(* Logix 5000 project; controller ICX35_AOI_1_8 1756-L63 rev 16.23; software revision 16.04 *)

TASK MainTask (continuous, watchdog 500 ms) : MainProgram

MODULES
   Local : 1756-L63 (ICP 0, rev 16.23)
      for_local_ICX35 : 1756-EN2T (ICP 1, Ethernet 192.160.0.246, rev 2.1)
         ICX35 : vendor 1 type 0 code 23 (Ethernet 192.168.0.250, rev 1.1)
END_MODULES

TYPE ICX35_CONTROL :   // Contains trigger bits for the functions supported by the ICX35. Bit should be set as 1 to trigger request and AOI will automa
STRUCT
   Get_Status : BOOL;   // Reads status data from ICX35
   Reset_Status : BOOL;   // Resets status counters from ICX35
   Write_SMS : BOOL;   // Sends SMS message to ICX35
   Read_SMS : BOOL;   // Reads SMS message from ICX35
   Clear_SMS : BOOL;   // Clears all SMS from ICX35
   Reboot : BOOL;   // Reboot ICX35
END_STRUCT
END_TYPE

TYPE ICX35_ModuleDef :   // Main ICX35 definition
STRUCT
   CONTROL : ICX35_CONTROL;   // Trigger bits used to request functions from ICX35
   STATUS : ICX35_STATUS;   // ICX35 status
   SMS : ICX35_SMS;   // SMS send and receive functions
   UTIL : ICX35_UTIL;   // Tags used for internal processing - do not update the values
END_STRUCT
END_TYPE

TYPE ICX35_SMS :   // Stores main SMS functions
STRUCT
   READ : ICX35_SMS_Read;   // Reads SMS data from ICX35
   WRITE : ICX35_SMS_Write;   // Writes SMS message to ICX35
END_STRUCT
END_TYPE

TYPE ICX35_SMS_Read :   // SMS data read from ICX35
STRUCT
   Date_Time : SINT[18];   // DateTime Stamp for received SMS text. MM/DD/YY HH:MM:SS
   Time_Zone : SINT[6];   // UTC =/- TZ
   Phone_Number : SINT[24];   // full number including prefixes country code etc..
   Message : SINT[160];   // Received the message text
END_STRUCT
END_TYPE

TYPE ICX35_SMS_Write :   // SMS data written to ICX35
STRUCT
   Message : LSTRING;
   Phone_Count : INT;   // Quantity of phone numbers that the SMS will be sent to. 5 is the limit.
   Phone_Number_1 : SINT[24];   // full number including prefixes country code (example +16613334455)
   Phone_Number_2 : SINT[24];   // full number including prefixes country code
   Phone_Number_3 : SINT[24];   // full number including prefixes country code
   Phone_Number_4 : SINT[24];   // full number including prefixes country code
   Phone_Number_5 : SINT[24];   // full number including prefixes country code
END_STRUCT
END_TYPE

TYPE ICX35_STATUS :   // ICX35 Status
STRUCT
   RSSI : SINT;   // Current Signal Strength dBm. Range -50 to -125
   Min_RSSI : SINT;   // Signal Strength Minimum(since power on). Range -50 to -125
   Max_RSSI : SINT;   // Signal Strength Maximum(since power on). Range -50 to -125
   Cell_Net_State : SINT;   // Status of the connection to the Cellular Network. 0: Disconnect, 1: Connecting, 2: Connected
   MAC_Address : SINT[6];   // MAC ID of ICX35
   WAN_IP : INT[4];   // Cellular network IP
   Cell_Net_Disconnects : DINT;   // Number of times Modem is disconnected from the cellular network since power on
   LAN_KBytes_Sent : DINT;   // Number Kbytes sent on LAN since power on
   LAN_KBytes_Received : DINT;   // Number of Kbytes received LAN since power on
   WAN_KBytes_Sent : DINT;   // Number of Bytes Sent WAN since power on
   WAN_KBytes_Received : DINT;   // Number of bytes received WAN since power on
   SMS_MSGs_Sent : DINT;   // Number of SMS Messages Sent since power on
   SMS_MSGs_Received : DINT;   // Number of SMS Messages Sent since power on
   SMS_MSGs_Rx_Free_Buffer_Counter : DINT;   // Number of free slots in the Rx SMS buffer out of 255 Message slots.
   PowerOnTime_Year : INT;   // Power on time year
   PowerOnTime_Month : INT;   // Power on time month
   PowerOnTime_Day : INT;   // Power on time day
   PowerOnTime_Hour : INT;   // Power on time hour
   PowerOnTime_Minute : INT;   // Power on time minute
   PowerOnTime_Second : INT;   // Power on time second
   Link_Time_Days : DINT;   // Link Time: Days of Cellular Connection.
   Link_Time_Hours : DINT;   // Link Time: Hours of Cellular Connection.
   Link_Time_Minutes : INT;   // Link Time: Minutes of Cellular Connection.
   Link_Time_Seconds : INT;   // Link Time: Seconds of Cellular Connection.
   Data_Usage_Current_Month : DINT;   // Data usage of current month in KB.
   Data_Usage_Previous_Month : DINT;   // Data usage of last month in KB.
   Data_Usage_Current_Day : DINT;   // Data usage for today in KB.
   Data_Usage_Previous_Day : DINT;   // Data usage of yesterday in KB.
   FW_Version : SINT[24];   // Firmware Version for the Gateway
   Phone_Number : SINT[18];   // Cellular phone number
   IMEI : SINT[20];   // IMEI number
END_STRUCT
END_TYPE

TYPE ICX35_UTIL :   // Internal tag used for internal ladder processing. Not to be updated by user application
STRUCT
   Status : SINT[149];   // Receives Raw Status Data from the Gateway
   SMSwrite : SINT[284];   // Text Messages (SMS) to be sent.
   SMSread : SINT[216];   // Text Messages that are read.
   SMSwritemsgstat : BOOL;   // SMS Write MSG instruction status.
   SMSreadmsgstat : BOOL;   // SMS Read MSG instruction status.
   ResetStatus : SINT;   // Reset speceific Status counters.
   Clear_SMS : SINT;   // Clear SMS Messages
   Reboot : SINT;   // Reboot ICX35 Gateway
END_STRUCT
END_TYPE

TYPE LSTRING :   // string type
STRUCT
   LEN : DINT;
   DATA : SINT[160];
END_STRUCT
END_TYPE

ADD_ON_INSTRUCTION AOI_ICX35   (* revision 1.8 *)
// Add-On Instruction for ICX35 Industrial Cellular Gateway
// Revision note:
// 1.8    2018/06/14.
// This Revision is compatible with ICX35 firmware version 1.4 and later.
VAR_IN_OUT
   ICX35 : ICX35_ModuleDef; {required}
   ICX35_MSG_GET_STATUS : MESSAGE; {required}
   ICX35_MSG_READ_SMS : MESSAGE; {required}
   ICX35_MSG_RESET_STATUS : MESSAGE; {required}
   ICX35_MSG_WRITE_SMS : MESSAGE; {required}
   ICX35_MSG_CLEAR_SMS : MESSAGE; {required}
   ICX35_MSG_REBOOT : MESSAGE; {required}
END_VAR

ROUTINE Logic   (* ladder *)
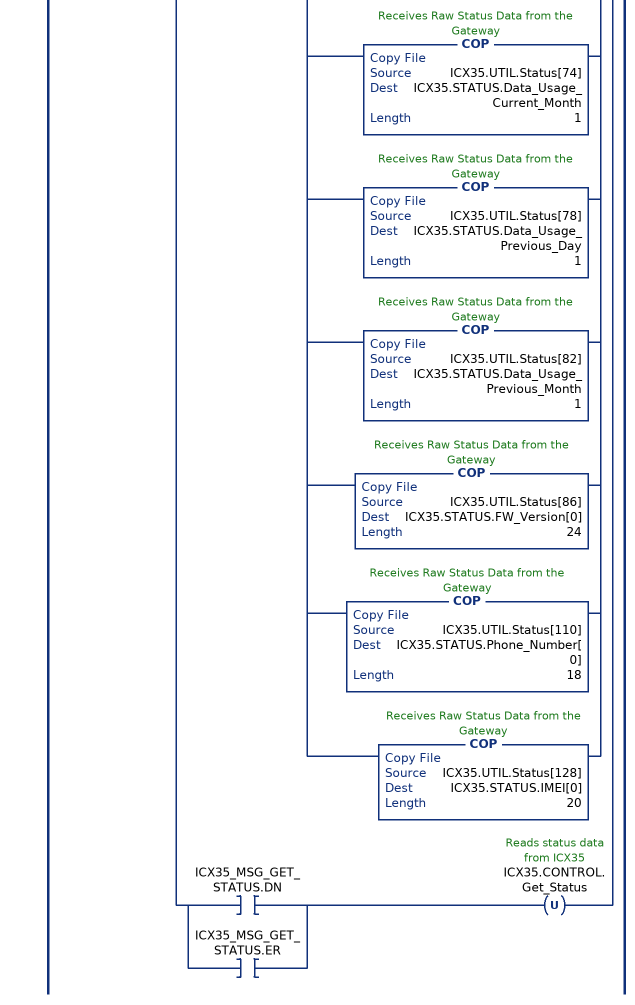
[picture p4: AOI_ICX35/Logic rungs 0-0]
   0: XIC(ICX35.CONTROL.Get_Status)[MSG(ICX35_MSG_GET_STATUS) ,XIC(ICX35_MSG_GET_STATUS.DN) [COP(ICX35.UTIL.Status[0],ICX35.STATUS.RSSI,4) ,COP(ICX35.UTIL.Status[4],ICX35.STATUS.MAC_Address[0],6) ,MVM(0,65280,ICX35.STATUS.WAN_IP[0]) ,MVM(ICX35.UTIL.Status[10],255,ICX35.STATUS.WAN_IP[0]) ,MVM(0,65280,ICX35.STATUS.WAN_IP[1]) ,MVM(ICX35.UTIL.Status[11],255,ICX35.STATUS.WAN_IP[1]) ,MVM(0,65280,ICX35.STATUS.WAN_IP[2]) ,MVM(ICX35.UTIL.Status[12],255,ICX35.STATUS.WAN_IP[2]) ,MVM(0,65280,ICX35.STATUS.WAN_IP[3]) ,MVM(ICX35.UTIL.Status[13],255,ICX35.STATUS.WAN_IP[3]) ,COP(ICX35.UTIL.Status[14],ICX35.STATUS.Cell_Net_Disconnects,1) ,COP(ICX35.UTIL.Status[18],ICX35.STATUS.LAN_KBytes_Sent,1) ,COP(ICX35.UTIL.Status[22],ICX35.STATUS.LAN_KBytes_Received,1) ,COP(ICX35.UTIL.Status[26],ICX35.STATUS.WAN_KBytes_Sent,1) ,COP(ICX35.UTIL.Status[30],ICX35.STATUS.WAN_KBytes_Received,1) ,COP(ICX35.UTIL.Status[34],ICX35.STATUS.SMS_MSGs_Sent,1) ,COP(ICX35.UTIL.Status[38],ICX35.STATUS.SMS_MSGs_Received,1) ,COP(ICX35.UTIL.Status[42],ICX35.STATUS.SMS_MSGs_Rx_Free_Buffer_Counter,1) ,COP(ICX35.UTIL.Status[46],ICX35.STATUS.PowerOnTime_Year,1) ,COP(ICX35.UTIL.Status[48],ICX35.STATUS.PowerOnTime_Month,1) ,COP(ICX35.UTIL.Status[50],ICX35.STATUS.PowerOnTime_Day,1) ,COP(ICX35.UTIL.Status[52],ICX35.STATUS.PowerOnTime_Hour,1) ,COP(ICX35.UTIL.Status[54],ICX35.STATUS.PowerOnTime_Minute,1) ,COP(ICX35.UTIL.Status[56],ICX35.STATUS.PowerOnTime_Second,1) ,COP(ICX35.UTIL.Status[58],ICX35.STATUS.Link_Time_Days,1) ,COP(ICX35.UTIL.Status[62],ICX35.STATUS.Link_Time_Hours,1) ,COP(ICX35.UTIL.Status[66],ICX35.STATUS.Link_Time_Minutes,1) ,COP(ICX35.UTIL.Status[68],ICX35.STATUS.Link_Time_Seconds,1) ,COP(ICX35.UTIL.Status[70],ICX35.STATUS.Data_Usage_Current_Day,1) ,COP(ICX35.UTIL.Status[74],ICX35.STATUS.Data_Usage_Current_Month,1) ,COP(ICX35.UTIL.Status[78],ICX35.STATUS.Data_Usage_Previous_Day,1) ,COP(ICX35.UTIL.Status[82],ICX35.STATUS.Data_Usage_Previous_Month,1) ,COP(ICX35.UTIL.Status[86],ICX35.STATUS.FW_Version[0],24) ,COP(ICX35.UTIL.Status[110],ICX35.STATUS.Phone_Number[0],18) ,COP(ICX35.UTIL.Status[128],ICX35.STATUS.IMEI[0],20) ] ,[XIC(ICX35_MSG_GET_STATUS.DN) ,XIC(ICX35_MSG_GET_STATUS.ER) ] OTU(ICX35.CONTROL.Get_Status) ];
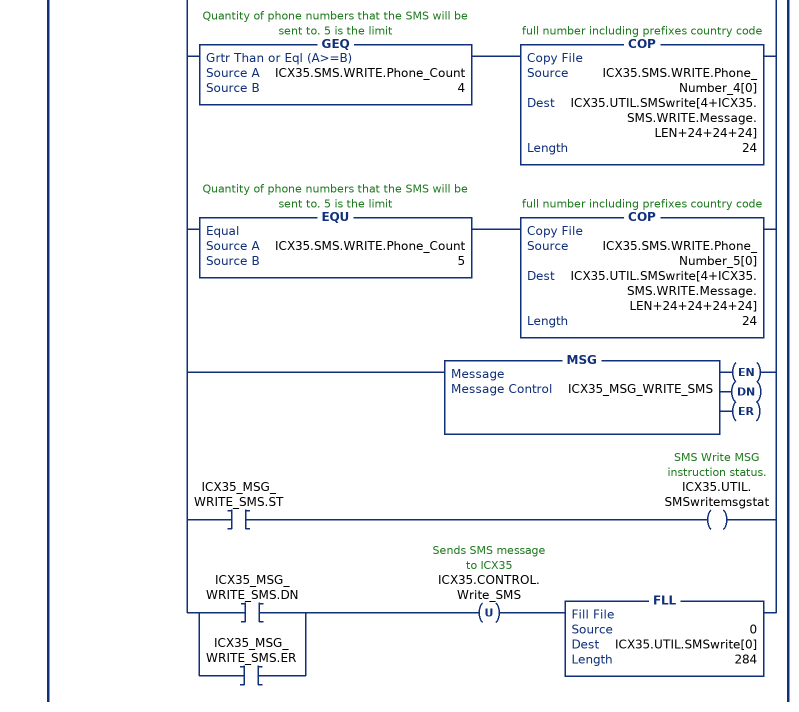
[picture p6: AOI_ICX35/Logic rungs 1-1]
   1: XIC(ICX35.CONTROL.Write_SMS)[LEQ(ICX35.SMS.WRITE.Message.LEN,160) COP(ICX35.SMS.WRITE.Message.LEN,ICX35.UTIL.SMSwrite[0],2) ,COP(ICX35.SMS.WRITE.Phone_Count,ICX35.UTIL.SMSwrite[2],2) ,COP(ICX35.SMS.WRITE.Message.DATA[0],ICX35.UTIL.SMSwrite[4],ICX35.SMS.WRITE.Message.LEN) ,COP(ICX35.SMS.WRITE.Phone_Number_1[0],ICX35.UTIL.SMSwrite[4+ICX35.SMS.WRITE.Message.LEN],24) ,GEQ(ICX35.SMS.WRITE.Phone_Count,2) COP(ICX35.SMS.WRITE.Phone_Number_2[0],ICX35.UTIL.SMSwrite[4+ICX35.SMS.WRITE.Message.LEN+24],24) ,GEQ(ICX35.SMS.WRITE.Phone_Count,3) COP(ICX35.SMS.WRITE.Phone_Number_3[0],ICX35.UTIL.SMSwrite[4+ICX35.SMS.WRITE.Message.LEN+24+24],24) ,GEQ(ICX35.SMS.WRITE.Phone_Count,4) COP(ICX35.SMS.WRITE.Phone_Number_4[0],ICX35.UTIL.SMSwrite[4+ICX35.SMS.WRITE.Message.LEN+24+24+24],24) ,EQU(ICX35.SMS.WRITE.Phone_Count,5) COP(ICX35.SMS.WRITE.Phone_Number_5[0],ICX35.UTIL.SMSwrite[4+ICX35.SMS.WRITE.Message.LEN+24+24+24+24],24) ,MSG(ICX35_MSG_WRITE_SMS) ,XIC(ICX35_MSG_WRITE_SMS.ST) OTE(ICX35.UTIL.SMSwritemsgstat) ,[XIC(ICX35_MSG_WRITE_SMS.DN) ,XIC(ICX35_MSG_WRITE_SMS.ER) ] OTU(ICX35.CONTROL.Write_SMS) FLL(0,ICX35.UTIL.SMSwrite[0],284) ];
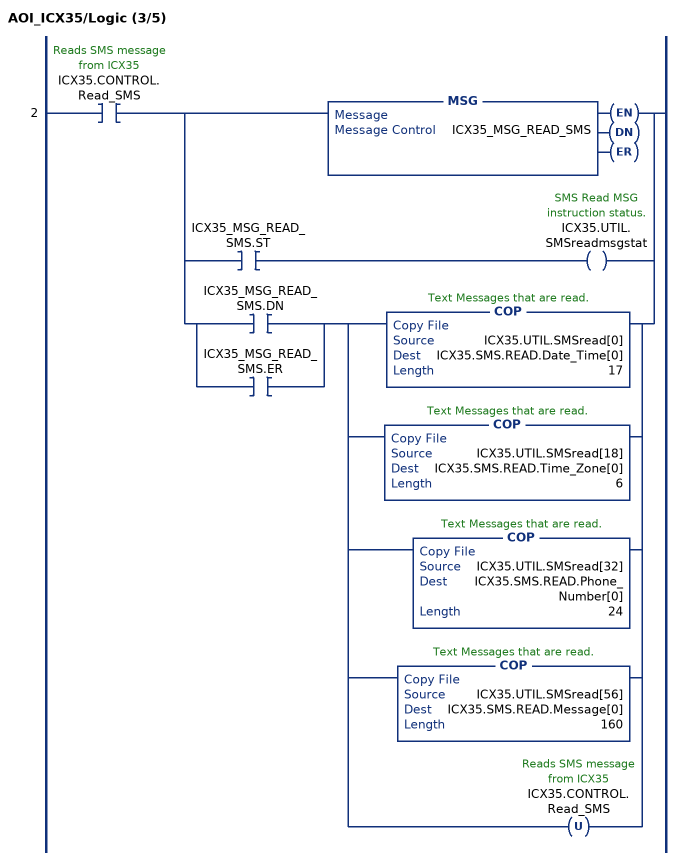
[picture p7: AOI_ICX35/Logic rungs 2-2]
   2: XIC(ICX35.CONTROL.Read_SMS)[MSG(ICX35_MSG_READ_SMS) ,XIC(ICX35_MSG_READ_SMS.ST) OTE(ICX35.UTIL.SMSreadmsgstat) ,[XIC(ICX35_MSG_READ_SMS.DN) ,XIC(ICX35_MSG_READ_SMS.ER) ] [COP(ICX35.UTIL.SMSread[0],ICX35.SMS.READ.Date_Time[0],17) ,COP(ICX35.UTIL.SMSread[18],ICX35.SMS.READ.Time_Zone[0],6) ,COP(ICX35.UTIL.SMSread[32],ICX35.SMS.READ.Phone_Number[0],24) ,COP(ICX35.UTIL.SMSread[56],ICX35.SMS.READ.Message[0],160) ,OTU(ICX35.CONTROL.Read_SMS) ] ];
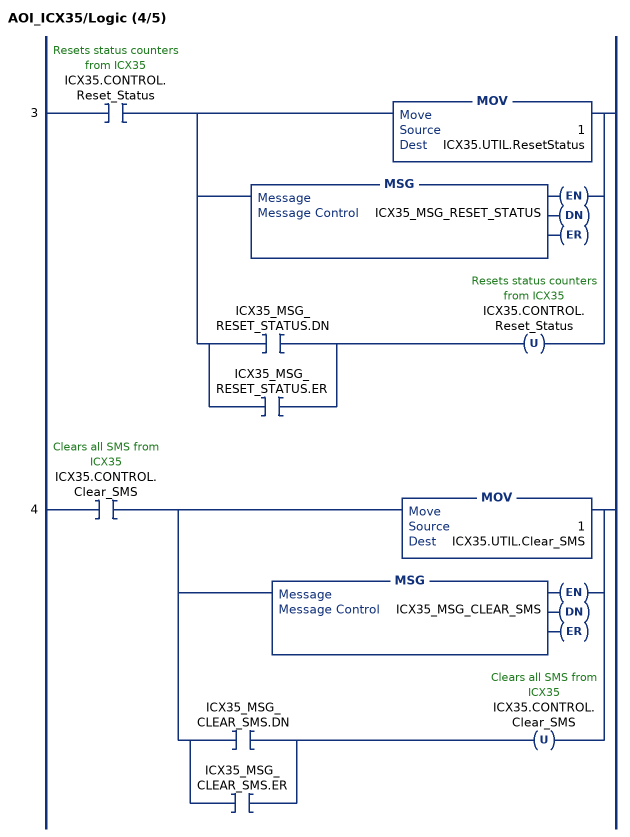
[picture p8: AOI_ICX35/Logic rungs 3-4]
   3: XIC(ICX35.CONTROL.Reset_Status)[MOV(1,ICX35.UTIL.ResetStatus) ,MSG(ICX35_MSG_RESET_STATUS) ,[XIC(ICX35_MSG_RESET_STATUS.DN) ,XIC(ICX35_MSG_RESET_STATUS.ER) ] OTU(ICX35.CONTROL.Reset_Status) ];
   4: XIC(ICX35.CONTROL.Clear_SMS)[MOV(1,ICX35.UTIL.Clear_SMS) ,MSG(ICX35_MSG_CLEAR_SMS) ,[XIC(ICX35_MSG_CLEAR_SMS.DN) ,XIC(ICX35_MSG_CLEAR_SMS.ER) ] OTU(ICX35.CONTROL.Clear_SMS) ];
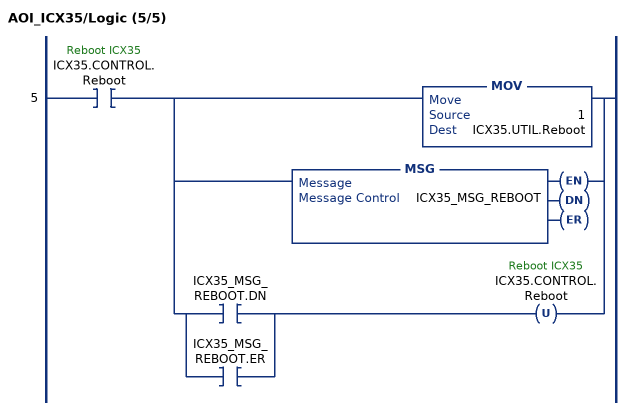
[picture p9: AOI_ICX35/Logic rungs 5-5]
   5: XIC(ICX35.CONTROL.Reboot)[MOV(1,ICX35.UTIL.Reboot) ,MSG(ICX35_MSG_REBOOT) ,[XIC(ICX35_MSG_REBOOT.DN) ,XIC(ICX35_MSG_REBOOT.ER) ] OTU(ICX35.CONTROL.Reboot) ];
END_ROUTINE
END_ADD_ON_INSTRUCTION

VAR_GLOBAL   (* controller tags *)
   AOI_ICX35 : AOI_ICX35;
   ICX35 : ICX35_ModuleDef;
   ICX35_MSG_GET_STATUS : MESSAGE;
        MessageParameters(ServiceCode := 16#0001, LocalElement := ICX35.UTIL.Status[0], DestinationTag := ICX35.UTIL.Status[0], ...)
   ICX35_MSG_MOD_REBOOT : MESSAGE;
        MessageParameters(ServiceCode := 16#0010, LocalElement := ICX35.UTIL.Reboot, ...)
   ICX35_MSG_READ_SMS : MESSAGE;
        MessageParameters(ServiceCode := 16#0001, LocalElement := ICX35.UTIL.SMSread[0], DestinationTag := ICX35.UTIL.SMSread[0], ...)
   ICX35_MSG_RESET_STATUS : MESSAGE;
        MessageParameters(ServiceCode := 16#0010, LocalElement := ICX35.UTIL.ResetStatus, ...)
   ICX35_MSG_SMS_CLEAR : MESSAGE;
        MessageParameters(ServiceCode := 16#0010, LocalElement := ICX35.UTIL.Clear_SMS, ...)
   ICX35_MSG_WRITE_SMS : MESSAGE;
        MessageParameters(ServiceCode := 16#0002, LocalElement := ICX35.UTIL.SMSwrite[0], DestinationTag := ICX35.UTIL.SMSwrite[0], ...)
END_VAR

PROGRAM MainProgram   (* main routine MainRoutine *)
VAR
   bit1 : DINT;
END_VAR

ROUTINE MainRoutine   (* ladder *)
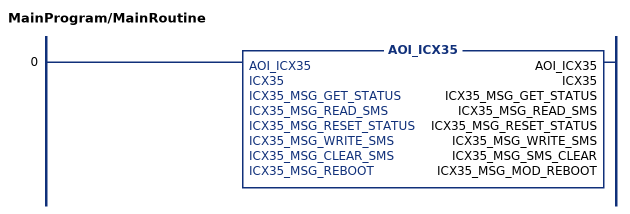
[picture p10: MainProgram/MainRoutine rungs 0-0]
   0: AOI_ICX35(AOI_ICX35,ICX35,ICX35_MSG_GET_STATUS,ICX35_MSG_READ_SMS,ICX35_MSG_RESET_STATUS,ICX35_MSG_WRITE_SMS,ICX35_MSG_SMS_CLEAR,ICX35_MSG_MOD_REBOOT);
END_ROUTINE
END_PROGRAM
